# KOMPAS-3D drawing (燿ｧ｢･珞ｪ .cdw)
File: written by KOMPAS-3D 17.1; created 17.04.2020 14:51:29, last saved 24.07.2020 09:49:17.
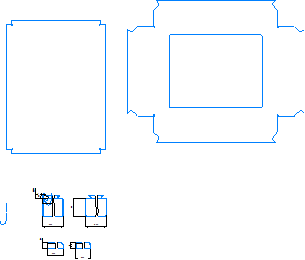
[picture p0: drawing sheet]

Sheet 1: A4, portrait

Title block, sheet 1: name: дверь; material: Сталь 10  ГОСТ 1050-2013; mass: 1,2; sheets: 1; sheet format: A4

Views: Вид 1, Развертка, Вид 2, Вид 3, Местный разрез 1, Спереди, Проекционный вид 4, Вид 5, Проекционный вид 6
Referenced files in E:\laser\Ящик_мойки\: дверь.m3d, Корпус_ящика.m3d
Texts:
  ex71
  Корпус_ящика
Dimensions and other numbers on the sheet: 15; 350; 250; 50; 11,53; 1:1; 1; 1,2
